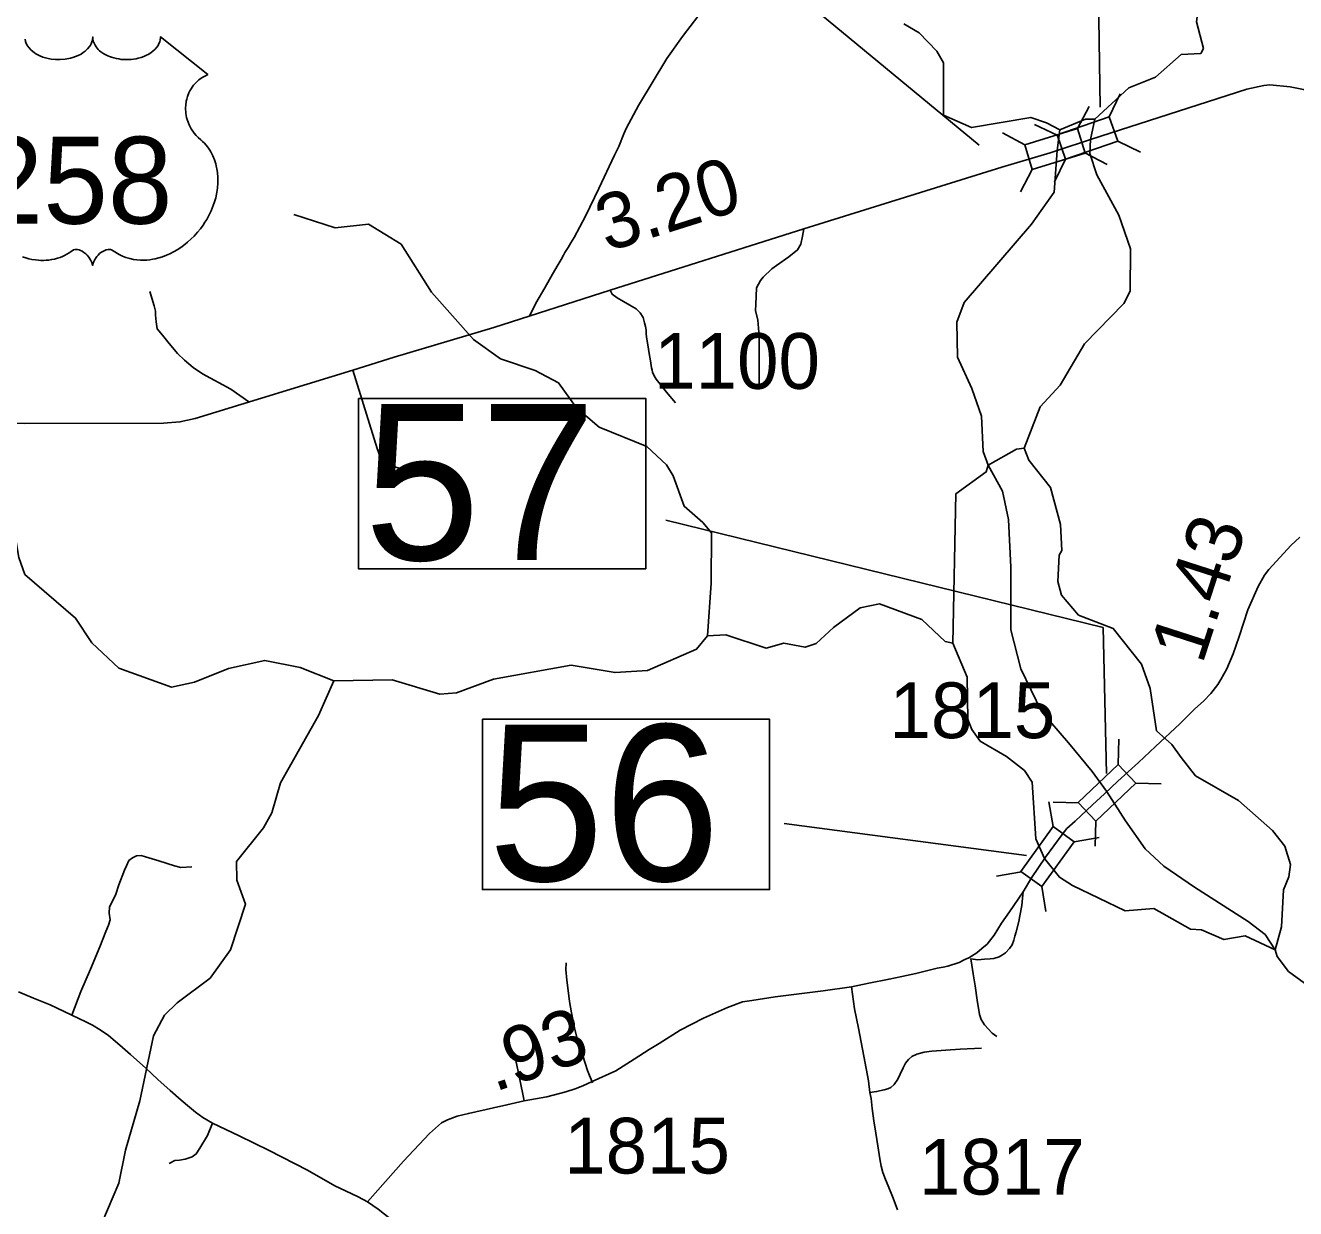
# Model space of a CAD drawing. Extents: x 2290615 to 2522933, y 819489 to 1012715.
# Drawn here: x 2451720 to 2463114, y 839929 to 850547 of the extents above; entities that cross this region are included whole.
import ezdxf

# ---------------------------------------------------------------- set-up
doc = ezdxf.new("R2010")
doc.units = 0
for name, color, linetype in [('Exist Hydrographic Creek Single Shore', 7, 'Continuous'), ('Exist Hydrographic Misc Water Feature', 7, 'Continuous'), ('Exist Road Non-System Type 51', 7, 'Continuous'), ('Exist Road Primary US Shield CELL', 7, 'Continuous'), ('Exist Road Primary US Shield Number Label', 7, 'Continuous'), ('Exist Road Secondary Mileage Hundredths English Label', 7, 'Continuous'), ('Exist Road Secondary Structure Standard Bridge CELL', 7, 'Continuous'), ('Exist Road Secondary Structure Standard Bridge Number Label', 7, 'Continuous'), ('Exist Road Secondary Type 51 Attributed', 7, 'Continuous'), ('Exist Road Secondary Type 51 Number Label', 7, 'Continuous')]:
    doc.layers.add(name, color=color, linetype=linetype)

msp = doc.modelspace()

# ---------------------------------------------------------------- linework, layer by layer
at = {"layer": 'Exist Hydrographic Creek Single Shore'}
for points in [[(2461314, 849705), (2461618, 849987), (2461858, 850082), (2462088, 850285), (2462263, 850295), (2462287, 850339), (2462225, 850579), (2462285, 851045)], [(2460355, 846600), (2460311, 846723), (2460298, 847041), (2460211, 847290), (2460081, 847570), (2460076, 847885), (2460140, 848062), (2460746, 848763), (2460950, 849050), (2460974, 849424), (2460999, 849610)], [(2460678, 846754), (2460822, 847124), (2461002, 847319), (2461221, 847689), (2461574, 848051), (2461630, 848162), (2461633, 848543), (2461528, 848844), (2461331, 849207), (2461269, 849398), (2461274, 849522), (2461314, 849705)], [(2460999, 849610), (2461231, 849705), (2461314, 849705)], [(2460355, 846600), (2460611, 846745), (2460678, 846754)], [(2462932, 842250), (2462987, 842459), (2463006, 842791), (2463055, 842908), (2463070, 843017), (2463017, 843182), (2462907, 843322), (2462602, 843592), (2462215, 843813), (2462088, 843978), (2462003, 844093), (2461867, 844216), (2461811, 844597), (2461733, 844814), (2461478, 845135), (2461168, 845254), (2461015, 845435), (2460980, 845558), (2460993, 845792), (2461017, 845836), (2461005, 846068), (2460917, 846399), (2460721, 846647), (2460678, 846754)], [(2460039, 845004), (2460067, 846345), (2460339, 846540), (2460355, 846600)], [(2460355, 846600), (2460484, 846367), (2460539, 846113), (2460560, 845687), (2460560, 845124), (2460649, 844773), (2460835, 844389), (2461076, 844109), (2461288, 843853), (2461419, 843674)], [(2462932, 842250), (2462663, 842377), (2462472, 842343), (2462271, 842430), (2462171, 842436), (2461843, 842622), (2461585, 842602), (2461114, 842829), (2460996, 842903), (2460863, 843072), (2460783, 843249), (2460750, 843756), (2460682, 843862), (2460521, 843987), (2460286, 844125), (2460209, 844230), (2460174, 844320), (2460168, 844698), (2460039, 845004)], [(2461419, 843674), (2461587, 843409), (2461766, 843157), (2461933, 843001), (2462208, 842815), (2462689, 842506), (2462840, 842389), (2462932, 842250)], [(2463528, 841926), (2463228, 841927), (2463051, 842058), (2462949, 842192), (2462932, 842250)]]:
    msp.add_lwpolyline(points, dxfattribs=at)
at = {"layer": 'Exist Hydrographic Misc Water Feature'}
for points in [[(2460999, 849610), (2460881, 849674), (2460739, 849721), (2460207, 849630), (2459956, 849741), (2459956, 850211), (2459896, 850317), (2459736, 850481), (2459601, 850561)], [(2457838, 845069), (2457872, 845543), (2457873, 845993), (2457797, 846085), (2457628, 846232), (2457532, 846504), (2457472, 846603), (2457294, 846767), (2456867, 846943), (2456664, 847115), (2456502, 847339), (2456292, 847451), (2455982, 847554), (2455738, 847728), (2455364, 848152), (2455091, 848584), (2454796, 848763), (2454497, 848731), (2454128, 848850)], [(2454486, 844666), (2454184, 844785), (2453867, 844848), (2453543, 844775), (2453236, 844654), (2453029, 844610), (2452559, 844778), (2452314, 845007), (2452169, 845228), (2451713, 845620), (2451661, 845772), (2451605, 846111), (2451334, 846382), (2451283, 846482), (2451242, 846940), (2451165, 847071), (2450954, 847293), (2450798, 847657)], [(2460039, 845004), (2459972, 845018), (2459760, 845216), (2459383, 845358), (2459209, 845322), (2458970, 845145), (2458814, 845000), (2458714, 844967), (2458522, 845005), (2458364, 844959), (2458004, 845079), (2457838, 845069)], [(2454486, 844666), (2455011, 844674), (2455438, 844547), (2455588, 844557), (2455919, 844679), (2456617, 844806), (2457010, 844740), (2457301, 844758), (2457740, 844950), (2457838, 845069)], [(2453065, 838095), (2452837, 838305), (2452648, 838685), (2452609, 838995), (2452522, 839218), (2452450, 839557), (2452407, 839667), (2452405, 839798), (2452558, 840159), (2452619, 840453), (2452746, 840895), (2452870, 841481), (2452967, 841666), (2453082, 841776), (2453378, 841998), (2453558, 842251), (2453693, 842661), (2453615, 842877), (2453612, 843045), (2453857, 843347), (2453930, 843481), (2454009, 843750), (2454349, 844355), (2454486, 844666)]]:
    msp.add_lwpolyline(points, dxfattribs=at)
at = {"layer": 'Exist Road Non-System Type 51'}
for points in [[(2457791, 850679), (2457615, 850448), (2457475, 850249), (2457219, 849829), (2457153, 849707), (2457112, 849629), (2457089, 849574), (2457042, 849461), (2457005, 849383), (2456864, 849084), (2456745, 848836), (2456641, 848644), (2456612, 848596), (2456589, 848555), (2456560, 848508), (2456548, 848485), (2456526, 848447), (2456499, 848402), (2456449, 848314), (2456379, 848192), (2456300, 848056), (2456241, 847939)], [(2457791, 850679), (2457615, 850448), (2457475, 850249), (2457219, 849829), (2457153, 849707), (2457112, 849629), (2457089, 849574), (2457042, 849461), (2457005, 849383), (2456864, 849084), (2456745, 848836), (2456641, 848644), (2456612, 848596), (2456589, 848555), (2456560, 848508), (2456548, 848485), (2456526, 848447), (2456499, 848402), (2456449, 848314), (2456379, 848192), (2456300, 848056), (2456241, 847939)], [(2458704, 848721), (2458691, 848655), (2458676, 848585), (2458647, 848532), (2458568, 848471), (2458458, 848393), (2458416, 848363), (2458339, 848289), (2458314, 848257), (2458279, 848193), (2458271, 848042), (2458268, 847988), (2458289, 847903), (2458302, 847759), (2458303, 847325)], [(2458704, 848721), (2458691, 848655), (2458676, 848585), (2458647, 848532), (2458568, 848471), (2458458, 848393), (2458416, 848363), (2458339, 848289), (2458314, 848257), (2458279, 848193), (2458271, 848042), (2458268, 847988), (2458289, 847903), (2458302, 847759), (2458303, 847325)], [(2453724, 847168), (2453561, 847284), (2453307, 847421), (2453224, 847478), (2453147, 847543), (2453084, 847602), (2452997, 847708), (2452950, 847767), (2452901, 847824), (2452892, 847886), (2452887, 847946), (2452886, 847982), (2452875, 848030), (2452835, 848159)], [(2453724, 847168), (2453561, 847284), (2453307, 847421), (2453224, 847478), (2453147, 847543), (2453084, 847602), (2452997, 847708), (2452950, 847767), (2452901, 847824), (2452892, 847886), (2452887, 847946), (2452886, 847982), (2452875, 848030), (2452835, 848159)], [(2456965, 848171), (2456983, 848134), (2457028, 848103), (2457199, 848004), (2457234, 847968), (2457262, 847927), (2457273, 847879), (2457281, 847844), (2457287, 847813), (2457288, 847783), (2457292, 847751), (2457303, 847681), (2457315, 847602), (2457326, 847538), (2457337, 847474), (2457341, 847454), (2457346, 847436), (2457361, 847402), (2457379, 847374), (2457471, 847255), (2457551, 847159)], [(2456965, 848171), (2456983, 848134), (2457028, 848103), (2457199, 848004), (2457234, 847968), (2457262, 847927), (2457273, 847879), (2457281, 847844), (2457287, 847813), (2457288, 847783), (2457292, 847751), (2457303, 847681), (2457315, 847602), (2457326, 847538), (2457337, 847474), (2457341, 847454), (2457346, 847436), (2457361, 847402), (2457379, 847374), (2457471, 847255), (2457551, 847159)], [(2454658, 847452), (2454874, 846751), (2454901, 846675), (2454928, 846634), (2454948, 846612), (2454980, 846601), (2455011, 846593), (2455063, 846578), (2455105, 846563), (2455149, 846533), (2455190, 846516), (2455224, 846509), (2455272, 846511), (2455308, 846518), (2455443, 846552)], [(2454658, 847452), (2454874, 846751), (2454901, 846675), (2454928, 846634), (2454948, 846612), (2454980, 846601), (2455011, 846593), (2455063, 846578), (2455105, 846563), (2455149, 846533), (2455190, 846516), (2455224, 846509), (2455272, 846511), (2455308, 846518), (2455443, 846552)], [(2452136, 841664), (2452218, 841877), (2452304, 842078), (2452386, 842278), (2452441, 842417), (2452466, 842474), (2452479, 842522), (2452470, 842582), (2452475, 842636), (2452509, 842705), (2452531, 842751), (2452559, 842834), (2452608, 842967), (2452627, 843005), (2452648, 843052), (2452680, 843078), (2452717, 843095), (2452757, 843098), (2452798, 843085), (2452918, 843049), (2453057, 843006), (2453113, 842991), (2453213, 842995)], [(2452136, 841664), (2452218, 841877), (2452304, 842078), (2452386, 842278), (2452441, 842417), (2452466, 842474), (2452479, 842522), (2452470, 842582), (2452475, 842636), (2452509, 842705), (2452531, 842751), (2452559, 842834), (2452608, 842967), (2452627, 843005), (2452648, 843052), (2452680, 843078), (2452717, 843095), (2452757, 843098), (2452798, 843085), (2452918, 843049), (2453057, 843006), (2453113, 842991), (2453213, 842995)], [(2460670, 842771), (2460665, 842716), (2460658, 842650), (2460642, 842557), (2460631, 842505), (2460609, 842413), (2460597, 842374), (2460586, 842338), (2460571, 842296), (2460549, 842263), (2460512, 842225), (2460486, 842206), (2460455, 842190), (2460407, 842173), (2460373, 842170), (2460325, 842167), (2460265, 842162), (2460200, 842170), (2460204, 842152), (2460223, 842035), (2460239, 841928), (2460258, 841800), (2460280, 841672), (2460295, 841625), (2460324, 841577), (2460391, 841505), (2460434, 841473)], [(2456806, 841059), (2456762, 841170), (2456719, 841299), (2456675, 841430), (2456645, 841550), (2456618, 841687), (2456600, 841787), (2456589, 841887), (2456577, 841978), (2456569, 842076), (2456570, 842136)], [(2456195, 840897), (2456153, 841103), (2456107, 841314)], [(2456195, 840897), (2456153, 841103), (2456107, 841314)], [(2459295, 840972), (2459355, 840979), (2459424, 840995), (2459457, 841003), (2459482, 841016), (2459513, 841044), (2459547, 841091), (2459566, 841135), (2459593, 841194), (2459616, 841234), (2459641, 841267), (2459673, 841293), (2459717, 841316), (2459781, 841332), (2459850, 841343), (2459976, 841350), (2460106, 841360), (2460296, 841370)], [(2459295, 840972), (2459355, 840979), (2459424, 840995), (2459457, 841003), (2459482, 841016), (2459513, 841044), (2459547, 841091), (2459566, 841135), (2459593, 841194), (2459616, 841234), (2459641, 841267), (2459673, 841293), (2459717, 841316), (2459781, 841332), (2459850, 841343), (2459976, 841350), (2460106, 841360), (2460296, 841370)], [(2453399, 840695), (2453353, 840586), (2453285, 840473), (2453252, 840420), (2453215, 840395), (2453153, 840372), (2453101, 840363), (2453059, 840360), (2453008, 840333)], [(2453399, 840695), (2453353, 840586), (2453285, 840473), (2453252, 840420), (2453215, 840395), (2453153, 840372), (2453101, 840363), (2453059, 840360), (2453008, 840333)]]:
    msp.add_lwpolyline(points, dxfattribs=at)
at = {"layer": 'Exist Road Primary US Shield CELL'}
msp.add_lwpolyline([(2451716, 850425), (2451720, 850404), (2451723, 850394), (2451733, 850373), (2451749, 850349), (2451772, 850325), (2451797, 850304), (2451814, 850293), (2451843, 850277), (2451876, 850263), (2451913, 850253), (2451950, 850245), (2451991, 850241), (2452031, 850240), (2452075, 850243), (2452123, 850253), (2452146, 850258), (2452170, 850267), (2452193, 850277), (2452219, 850290), (2452239, 850303), (2452255, 850315), (2452278, 850336), (2452296, 850359), (2452303, 850371), (2452310, 850383), (2452319, 850409), (2452321, 850420), (2452323, 850444), (2452324, 850424), (2452326, 850412), (2452330, 850400), (2452335, 850387), (2452344, 850369), (2452354, 850354), (2452373, 850331), (2452385, 850320), (2452395, 850311), (2452424, 850292), (2452458, 850275), (2452475, 850267), (2452492, 850261), (2452513, 850255), (2452536, 850249), (2452558, 850246), (2452580, 850242), (2452603, 850241), (2452622, 850240), (2452645, 850240), (2452667, 850242), (2452688, 850244), (2452713, 850248), (2452732, 850252), (2452757, 850259), (2452781, 850268), (2452801, 850276), (2452827, 850290), (2452849, 850303), (2452864, 850316), (2452883, 850333), (2452900, 850353), (2452911, 850368), (2452918, 850384), (2452925, 850400), (2452929, 850417), (2452931, 850432), (2452931, 850444), (2453356, 850106), (2453346, 850102), (2453323, 850090), (2453305, 850080), (2453276, 850059), (2453263, 850048), (2453251, 850036), (2453239, 850023), (2453229, 850012), (2453217, 849994), (2453206, 849977), (2453195, 849959), (2453187, 849942), (2453174, 849908), (2453167, 849886), (2453163, 849868), (2453158, 849830), (2453157, 849812), (2453157, 849794), (2453158, 849775), (2453160, 849757), (2453163, 849738), (2453166, 849722), (2453172, 849702), (2453179, 849678), (2453188, 849655), (2453208, 849618), (2453233, 849580), (2453251, 849559), (2453268, 849541), (2453294, 849519), (2453309, 849507), (2453325, 849490), (2453352, 849459), (2453362, 849445), (2453373, 849429), (2453383, 849412), (2453393, 849394), (2453401, 849378), (2453416, 849341), (2453427, 849306), (2453432, 849287), (2453440, 849246), (2453443, 849225), (2453446, 849184), (2453447, 849135), (2453443, 849088), (2453434, 849034), (2453427, 849001), (2453416, 848963), (2453405, 848930), (2453385, 848882), (2453368, 848847), (2453346, 848806), (2453330, 848781), (2453313, 848754), (2453290, 848723), (2453264, 848691), (2453233, 848656), (2453207, 848631), (2453174, 848601), (2453154, 848585), (2453126, 848563), (2453086, 848537), (2453048, 848515), (2453015, 848498), (2452986, 848485), (2452948, 848471), (2452885, 848454), (2452862, 848449), (2452835, 848445), (2452810, 848442), (2452785, 848441), (2452752, 848441), (2452719, 848443), (2452688, 848448), (2452656, 848455), (2452622, 848465), (2452591, 848477), (2452560, 848492), (2452507, 848525), (2452492, 848533), (2452484, 848536), (2452463, 848537), (2452444, 848532), (2452425, 848525), (2452413, 848518), (2452397, 848508), (2452385, 848499), (2452371, 848485), (2452361, 848473), (2452353, 848464), (2452338, 848441), (2452333, 848430), (2452327, 848415), (2452322, 848394), (2452316, 848421), (2452308, 848439), (2452299, 848454), (2452290, 848467), (2452275, 848484), (2452261, 848497), (2452245, 848510), (2452228, 848520), (2452215, 848527), (2452202, 848532), (2452187, 848536), (2452174, 848537), (2452164, 848537), (2452150, 848533), (2452130, 848519), (2452112, 848507), (2452092, 848495), (2452069, 848482), (2452051, 848474), (2452031, 848466), (2452007, 848458), (2451981, 848451), (2451954, 848446), (2451930, 848442), (2451905, 848440), (2451882, 848439), (2451858, 848439), (2451836, 848441), (2451810, 848443), (2451778, 848448), (2451751, 848454), (2451723, 848462), (2451694, 848471)], dxfattribs=at)
at = {"layer": 'Exist Road Secondary Structure Standard Bridge CELL'}
for p, q in [((2461541, 849932), (2461443, 849728)), ((2461158, 849621), (2461264, 849821)), ((2460976, 849561), (2460772, 849659)), ((2460484, 849582), (2460684, 849476)), ((2461723, 849411), (2461519, 849510)), ((2461225, 849404), (2461425, 849298)), ((2461051, 849347), (2460952, 849143)), ((2460646, 849055), (2460752, 849255)), ((2461529, 844142), (2461523, 843916)), ((2461909, 843742), (2461682, 843748)), ((2460902, 843580), (2460939, 843357)), ((2461166, 843571), (2460940, 843577)), ((2461322, 843407), (2461316, 843181)), ((2461351, 843259), (2461128, 843222)), ((2460654, 842951), (2460431, 842914)), ((2460838, 842820), (2460875, 842596))]:
    msp.add_line(p, q, dxfattribs=at)
for points in [[(2461519, 849510), (2461051, 849346), (2460975, 849565), (2461443, 849728)], [(2460684, 849476), (2461158, 849622), (2461226, 849400), (2460752, 849255)], [(2461682, 843748), (2461323, 843406), (2461163, 843574), (2461523, 843916)], [(2461128, 843222), (2460839, 842819), (2460651, 842954), (2460939, 843357)]]:
    msp.add_lwpolyline(points, close=True, dxfattribs=at)
at = {"layer": 'Exist Road Secondary Structure Standard Bridge Number Label'}
for p, q in [((2461360, 849813), (2461324, 852621)), ((2460276, 849472), (2456892, 852269)), ((2460699, 843099), (2458525, 843386))]:
    msp.add_line(p, q, dxfattribs=at)
for points in [[(2454707, 847200), (2457284, 847200), (2457284, 845671), (2454707, 845671)], [(2455819, 844321), (2458395, 844321), (2458395, 842792), (2455819, 842792)]]:
    msp.add_lwpolyline(points, close=True, dxfattribs=at)
msp.add_lwpolyline([(2461418, 843835), (2461387, 845143), (2457464, 846108)], dxfattribs=at)
at = {"layer": 'Exist Road Secondary Type 51 Attributed'}
for points in [[(2461274, 849522), (2462677, 849976), (2462830, 850008), (2462882, 850013), (2463065, 849995), (2463185, 849971), (2463890, 849852), (2464100, 849801), (2464758, 849560), (2464918, 849491)], [(2460983, 849428), (2461274, 849522)], [(2448491, 848054), (2449041, 847835), (2449886, 847465), (2449892, 847468), (2450905, 847059), (2450992, 847030), (2451177, 846991), (2451298, 846982), (2451712, 846975), (2452959, 846977), (2453106, 846989), (2453243, 847019), (2454658, 847452), (2455029, 847571), (2455923, 847836), (2456965, 848171), (2458704, 848721), (2460479, 849276), (2460912, 849405), (2460983, 849428)], [(2463152, 845956), (2463073, 845880), (2462942, 845740), (2462873, 845664), (2462834, 845614), (2462778, 845511), (2462686, 845303), (2462609, 845064), (2462555, 844907), (2462499, 844773), (2462444, 844676), (2462416, 844632), (2462354, 844552), (2462290, 844485), (2462208, 844410), (2462076, 844279), (2461858, 844076), (2461705, 843933), (2461519, 843764), (2461399, 843652), (2461293, 843552), (2461138, 843406), (2461062, 843339), (2461019, 843286), (2460871, 843082)], [(2460871, 843082), (2460746, 842899), (2460670, 842771), (2460549, 842591), (2460477, 842490), (2460411, 842383), (2460347, 842301), (2460300, 842264)], [(2460300, 842264), (2460255, 842226), (2460182, 842180), (2460148, 842164), (2460096, 842138), (2459996, 842105), (2459954, 842096), (2459899, 842086), (2459709, 842039), (2459583, 842013), (2459467, 841989), (2459285, 841951), (2459131, 841920)], [(2454789, 839989), (2454704, 840034), (2454590, 840088), (2454494, 840134), (2454251, 840273), (2453907, 840450), (2453637, 840582), (2453399, 840695), (2453311, 840747), (2453246, 840794), (2453192, 840839), (2453118, 840901), (2453018, 840990), (2452909, 841088), (2452801, 841189), (2452663, 841313), (2452567, 841397), (2452464, 841482), (2452389, 841533), (2452320, 841575), (2452263, 841606), (2452198, 841636), (2452136, 841664), (2452004, 841728), (2451943, 841757), (2451792, 841818), (2451657, 841875)], [(2459131, 841920), (2458877, 841885), (2458447, 841829), (2458237, 841797), (2458154, 841784), (2458017, 841734), (2457802, 841637), (2457593, 841531), (2457405, 841412), (2457314, 841358), (2457182, 841271), (2457016, 841166), (2456805, 841069), (2456721, 841031), (2456650, 841004), (2456568, 840976), (2456398, 840932), (2456195, 840897), (2456039, 840860), (2455920, 840835), (2455694, 840784), (2455592, 840760), (2455507, 840726), (2455453, 840698), (2455344, 840603), (2455111, 840355), (2454789, 839989)], [(2459131, 841920), (2459157, 841721), (2459193, 841548), (2459241, 841297), (2459283, 841076), (2459295, 840972), (2459306, 840918), (2459317, 840829), (2459332, 840717), (2459349, 840607), (2459368, 840492), (2459386, 840376), (2459397, 840311), (2459412, 840252), (2459436, 840189), (2459458, 840135), (2459504, 840022), (2459544, 839917)], [(2459691, 837113), (2459543, 837198), (2459325, 837320), (2459190, 837390), (2458960, 837510), (2458748, 837600), (2458526, 837704), (2458248, 837851), (2457723, 838125), (2457325, 838332), (2456744, 838628), (2456435, 838782), (2456257, 838894), (2456079, 839025), (2455933, 839133), (2455708, 839288), (2455436, 839493), (2455274, 839620), (2455102, 839751), (2454998, 839835), (2454884, 839925), (2454789, 839989)]]:
    msp.add_lwpolyline(points, dxfattribs=at)

# ---------------------------------------------------------------- texts
at = {"layer": 'Exist Road Primary US Shield Number Label'}
msp.add_text('258', height=780, dxfattribs=at).set_placement((2451299, 848768))
at = {"layer": 'Exist Road Secondary Mileage Hundredths English Label'}
for s, rotation, p in [('3.20', 17.5656, (2456936, 848512)), ('1.43', 72.1179, (2462277, 844804)), ('.93', 19.159, (2455927, 840974))]:
    msp.add_text(s, height=500, rotation=rotation, dxfattribs=at).set_placement(p)
at = {"layer": 'Exist Road Secondary Structure Standard Bridge Number Label'}
for s, p in [('57', (2454758, 845750)), ('56', (2455869, 842871))]:
    msp.add_text(s, height=1400, dxfattribs=at).set_placement(p)
at = {"layer": 'Exist Road Secondary Type 51 Number Label'}
for s, p in [('1100', (2457360, 847286)), ('1815', (2459471, 844151)), ('1815', (2456553, 840244)), ('1817', (2459735, 840055))]:
    msp.add_text(s, height=500, rotation=360, dxfattribs=at).set_placement(p)

doc.saveas('drawing.dxf')
